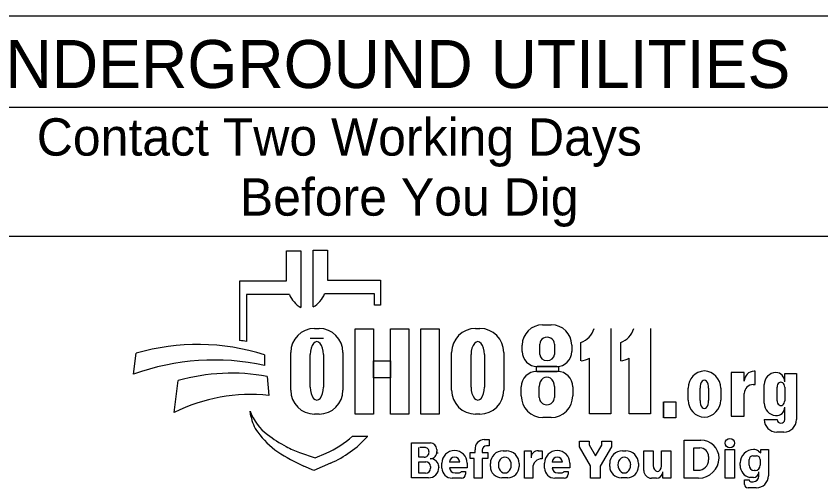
# Model space of a CAD drawing. Extents: x -20.5 to 34, y -66 to 23.9.
# Drawn here: x 15.219 to 18.236, y 1.67 to 3.439 of the extents above; entities that cross this region are included whole.
import ezdxf

# ---------------------------------------------------------------- set-up
doc = ezdxf.new("R2010")
doc.units = 0
doc.layers.add('SH_Data', color=7, linetype='Continuous')
doc.layers.add('SH_Text', color=7, linetype='Continuous')

msp = doc.modelspace()

# ---------------------------------------------------------------- linework, layer by layer
at = {"layer": 'SH_Data'}
for p, q in [((19.1267, 3.4394), (14.8767, 3.4394)), ((14.8767, 3.0978), (19.1267, 3.0978)), ((14.8767, 2.6144), (19.1267, 2.6144))]:
    msp.add_line(p, q, dxfattribs=at)
at = {"layer": 'SH_Text'}
for p, q in [((16.2327, 2.4474), (16.2327, 2.5589)), ((16.2327, 2.5589), (16.2864, 2.5589)), ((16.2864, 2.5589), (16.2864, 2.3468)), ((16.332, 2.3491), (16.332, 2.5612)), ((16.332, 2.5612), (16.3857, 2.5612)), ((16.3857, 2.5612), (16.3857, 2.4497)), ((16.0568, 2.2235), (16.0568, 2.4474)), ((16.0568, 2.4474), (16.2327, 2.4474)), ((16.3857, 2.4497), (16.5849, 2.4497)), ((16.5849, 2.4497), (16.5849, 2.3559)), ((16.082, 2.3959), (16.082, 2.2191)), ((16.2431, 2.3959), (16.082, 2.3959)), ((16.5616, 2.3983), (16.3753, 2.3983)), ((16.5616, 2.3559), (16.5616, 2.3983)), ((16.5849, 2.3559), (16.5616, 2.3559)), ((16.3377, 2.2682), (16.3543, 2.2682)), ((16.9408, 2.2682), (16.9573, 2.2682)), ((17.1923, 2.2822), (17.225, 2.2822)), ((17.4478, 2.2678), (17.4478, 1.9478)), ((17.5967, 2.2678), (17.5967, 1.9478)), ((16.371, 2.2312), (16.3212, 2.2312)), ((17.116, 2.1816), (17.116, 2.2059)), ((17.1821, 2.1702), (17.1821, 2.2095)), ((17.2363, 2.2095), (17.2363, 2.1702)), ((17.3013, 2.2059), (17.3013, 2.1816)), ((17.3362, 2.1471), (17.3362, 2.2152)), ((17.4851, 2.1471), (17.4851, 2.2152)), ((15.6594, 2.0972), (15.6688, 2.1753)), ((16.2482, 2.0367), (16.2482, 2.1787)), ((16.4437, 2.1787), (16.4437, 2.0367)), ((16.8513, 2.0367), (16.8513, 2.1787)), ((17.0468, 2.1787), (17.0468, 2.0367)), ((16.1501, 2.1688), (16.1501, 2.13)), ((16.3212, 2.0481), (16.3212, 2.1705)), ((16.3709, 2.1705), (16.3709, 2.0481)), ((16.9242, 2.0481), (16.9242, 2.1705)), ((16.974, 2.1705), (16.974, 2.0481)), ((17.3686, 1.9478), (17.3686, 2.1564)), ((17.5174, 1.9478), (17.5174, 2.1564)), ((17.2453, 2.1256), (17.172, 2.1256)), ((16.16, 2.0882), (16.1663, 2.0173)), ((17.1702, 2.1073), (17.2475, 2.1073)), ((17.9485, 2.1027), (17.8996, 2.1027)), ((17.8996, 2.1027), (17.8996, 1.9397)), ((17.9485, 2.0711), (17.9485, 2.1027)), ((17.9892, 2.1078), (17.9852, 2.1078)), ((17.9892, 2.0579), (17.9892, 2.1078)), ((18.1, 2.0685), (18.1, 2.0995)), ((18.1, 2.0995), (18.1436, 2.0995)), ((18.1436, 2.0995), (18.1436, 1.9266)), ((15.8112, 1.9527), (15.8259, 2.0728)), ((17.9815, 2.0579), (17.9892, 2.0579)), ((18.0231, 1.9881), (18.0231, 2.0577)), ((17.1123, 2.0154), (17.1123, 2.0494)), ((17.1798, 2.0094), (17.1798, 2.0503)), ((17.2366, 2.0503), (17.2366, 2.0094)), ((17.3054, 2.0494), (17.3054, 2.0154)), ((17.7376, 1.9995), (17.7376, 2.0449)), ((17.7827, 1.9987), (17.7827, 2.0449)), ((17.8148, 2.0449), (17.8148, 1.9987)), ((17.8598, 2.0449), (17.8598, 1.9995)), ((17.9485, 1.9397), (17.9485, 2.025)), ((18.0714, 1.9974), (18.0714, 2.0484)), ((18.1, 2.0484), (18.1, 1.9974)), ((17.6447, 1.9928), (17.6447, 1.9327)), ((18.1, 1.9266), (18.1, 1.973)), ((16.0989, 1.9398), (16.0959, 1.9577)), ((16.3543, 1.9473), (16.3377, 1.9473)), ((16.9573, 1.9473), (16.9408, 1.9473)), ((17.2244, 1.9344), (17.1932, 1.9344)), ((17.4478, 1.9478), (17.3686, 1.9478)), ((17.5967, 1.9478), (17.5174, 1.9478)), ((17.8996, 1.9397), (17.9485, 1.9397)), ((18.0231, 1.9266), (18.0714, 1.9266)), ((18.0968, 1.8799), (18.0699, 1.8799)), ((16.4792, 1.8639), (16.5366, 1.8639)), ((16.9731, 1.8517), (16.9925, 1.8517)), ((16.9925, 1.8517), (16.9925, 1.8287)), ((17.3311, 1.8461), (17.3669, 1.8461)), ((17.3311, 1.8246), (17.3311, 1.8461)), ((17.3669, 1.8461), (17.3669, 1.8325)), ((17.4142, 1.831), (17.4142, 1.8461)), ((17.4142, 1.8461), (17.4501, 1.8461)), ((17.4501, 1.8461), (17.4501, 1.8246)), ((17.7235, 1.8497), (17.7858, 1.8497)), ((17.7235, 1.7069), (17.7235, 1.8497)), ((16.7005, 1.7081), (16.7005, 1.8389)), ((16.7005, 1.8389), (16.7717, 1.8389)), ((16.7285, 1.7854), (16.7285, 1.8223)), ((16.7537, 1.8223), (16.7324, 1.8223)), ((16.7954, 1.8151), (16.7954, 1.8072)), ((16.9398, 1.8033), (16.9398, 1.8137)), ((16.9659, 1.8117), (16.9659, 1.8033)), ((16.9925, 1.8282), (16.9824, 1.8282)), ((17.3724, 1.7536), (17.3311, 1.8246)), ((17.3669, 1.8325), (17.391, 1.7911)), ((17.391, 1.7911), (17.4142, 1.831)), ((17.4501, 1.8246), (17.408, 1.7523)), ((17.7595, 1.7363), (17.7595, 1.8204)), ((17.7595, 1.8204), (17.782, 1.8204)), ((17.8761, 1.814), (17.9118, 1.814)), ((17.8761, 1.7069), (17.8761, 1.814)), ((17.9118, 1.814), (17.9118, 1.7069)), ((18.0099, 1.8144), (18.0386, 1.8144)), ((18.0099, 1.8018), (18.0099, 1.8144)), ((18.0099, 1.8144), (18.0386, 1.8144)), ((18.0386, 1.8144), (18.0386, 1.7158)), ((16.2808, 1.8035), (16.3402, 1.783)), ((16.3402, 1.783), (16.3812, 1.8008)), ((16.7479, 1.7854), (16.7285, 1.7854)), ((16.9205, 1.7803), (16.9205, 1.8033)), ((16.9205, 1.8033), (16.9398, 1.8033)), ((16.9354, 1.7803), (16.9205, 1.7803)), ((16.9354, 1.7069), (16.9354, 1.7803)), ((16.9659, 1.8033), (16.9875, 1.8033)), ((16.9875, 1.7803), (16.9659, 1.7803)), ((16.9659, 1.7803), (16.9659, 1.7069)), ((16.9875, 1.8033), (16.9875, 1.7803)), ((17.0443, 1.8099), (17.0564, 1.8099)), ((17.1245, 1.7069), (17.1245, 1.8096)), ((17.1245, 1.8096), (17.1491, 1.8096)), ((17.1491, 1.8096), (17.1491, 1.7827)), ((17.1763, 1.8096), (17.1902, 1.8096)), ((17.1902, 1.8096), (17.1902, 1.78)), ((17.4917, 1.8099), (17.5039, 1.8099)), ((17.5719, 1.8099), (17.6066, 1.8099)), ((17.5719, 1.7353), (17.5719, 1.8099)), ((17.6066, 1.8099), (17.6066, 1.7545)), ((17.638, 1.7528), (17.638, 1.8099)), ((17.638, 1.8099), (17.6728, 1.8099)), ((17.6728, 1.8099), (17.6728, 1.7069)), ((17.8146, 1.7877), (17.8146, 1.7759)), ((17.9808, 1.791), (17.9935, 1.791)), ((18.0013, 1.8084), (18.0099, 1.8018)), ((16.3342, 1.736), (16.2968, 1.7525)), ((16.3975, 1.7635), (16.3342, 1.736)), ((16.7285, 1.726), (16.7285, 1.7688)), ((16.7285, 1.7688), (16.754, 1.7688)), ((16.7721, 1.7507), (16.7721, 1.7443)), ((16.815, 1.7449), (16.815, 1.7633)), ((16.8816, 1.7673), (16.8431, 1.7673)), ((16.9096, 1.7633), (16.9096, 1.7457)), ((16.9965, 1.7512), (16.9965, 1.762)), ((17.1042, 1.762), (17.1042, 1.7512)), ((17.2, 1.7449), (17.2, 1.7633)), ((17.2665, 1.7673), (17.228, 1.7673)), ((17.2945, 1.7633), (17.2945, 1.7457)), ((17.3724, 1.7069), (17.3724, 1.7536)), ((17.408, 1.7523), (17.408, 1.7069)), ((17.4439, 1.7512), (17.4439, 1.762)), ((17.5517, 1.762), (17.5517, 1.7512)), ((17.9327, 1.7544), (17.9327, 1.7645)), ((17.9662, 1.7552), (17.9662, 1.7764)), ((18.0082, 1.7764), (18.0082, 1.7552)), ((16.7537, 1.726), (16.7285, 1.726)), ((16.8035, 1.7478), (16.8035, 1.7475)), ((16.9096, 1.7457), (16.8432, 1.7457)), ((16.8641, 1.7264), (16.8782, 1.7264)), ((16.8868, 1.732), (16.9036, 1.732)), ((16.9036, 1.732), (16.9036, 1.7222)), ((17.1551, 1.7451), (17.1551, 1.7069)), ((17.2945, 1.7457), (17.2281, 1.7457)), ((17.249, 1.7264), (17.2631, 1.7264)), ((17.2717, 1.732), (17.2886, 1.732)), ((17.2886, 1.732), (17.2886, 1.7222)), ((17.6431, 1.7069), (17.6431, 1.731)), ((17.7751, 1.7363), (17.7595, 1.7363)), ((17.9888, 1.7359), (17.9855, 1.7359)), ((18.003, 1.7148), (18.003, 1.7302)), ((16.7642, 1.7081), (16.7005, 1.7081)), ((16.8884, 1.7069), (16.853, 1.7069)), ((16.9659, 1.7069), (16.9354, 1.7069)), ((17.0615, 1.7085), (17.0393, 1.7085)), ((17.1551, 1.7069), (17.1245, 1.7069)), ((17.2733, 1.7069), (17.2379, 1.7069)), ((17.408, 1.7069), (17.3724, 1.7069)), ((17.5089, 1.7085), (17.4867, 1.7085)), ((17.6191, 1.7069), (17.6002, 1.7069)), ((17.6728, 1.7069), (17.6431, 1.7069)), ((17.7771, 1.7069), (17.7235, 1.7069)), ((17.9118, 1.7069), (17.8761, 1.7069)), ((17.9492, 1.6836), (17.9492, 1.7006)), ((17.9492, 1.7006), (17.9662, 1.7006)), ((17.9827, 1.7097), (17.969, 1.7097)), ((17.973, 1.6936), (17.9819, 1.6936)), ((17.9933, 1.6705), (17.9623, 1.6705))]:
    msp.add_line(p, q, dxfattribs=at)
for points in [[(16.4901, 2.2672), (16.5581, 2.2672), (16.5581, 1.9472), (16.4901, 1.9472)], [(16.6223, 2.2672), (16.6903, 2.2672), (16.6903, 1.9472), (16.6223, 1.9472)], [(16.7356, 2.2672), (16.8044, 2.2672), (16.8044, 1.9472), (16.7356, 1.9472)], [(16.5581, 2.1473), (16.6223, 2.1473), (16.6223, 2.0833), (16.5581, 2.0833)], [(17.1698, 2.1256), (17.2515, 2.1256), (17.2515, 2.1072), (17.1698, 2.1072)], [(17.6472, 1.9928), (17.6913, 1.9928), (17.6913, 1.9327), (17.6472, 1.9327)]]:
    msp.add_lwpolyline(points, close=True, dxfattribs=at)
msp.add_circle((17.8944, 1.8383), 0.0177, dxfattribs=at)
for centre, radius, start, end in [((16.3345, 2.4327), 0.0985, 201.9296, 240.7469), ((16.2839, 2.435), 0.0985, 299.2531, 338.0704), ((16.3377, 2.1787), 0.0895, 90, 180), ((16.3543, 2.1787), 0.0895, 0, 90), ((16.9408, 2.1787), 0.0895, 90, 180), ((16.9573, 2.1787), 0.0895, 0, 90), ((17.1923, 2.2059), 0.0763, 90, 180), ((17.225, 2.2059), 0.0763, 0, 90), ((17.3023, 2.297), 0.0885, 292.5572, 340.7355), ((17.4511, 2.297), 0.0885, 292.5572, 340.7355), ((15.8989, 1.3892), 0.8191, 72.1402, 106.3144), ((15.9286, 1.4145), 0.8191, 79.2074, 81.0007), ((17.172, 2.1816), 0.056, 180, 270), ((17.2453, 2.1816), 0.056, 270, 0), ((15.9619, 1.2581), 0.8919, 77.8238, 109.8274), ((17.3283, 2.2352), 0.0885, 275.1733, 297.0931), ((17.4771, 2.2352), 0.0885, 275.1733, 297.0931), ((16.0258, 1.3685), 0.7322, 79.44, 105.8467), ((17.1702, 2.0494), 0.0579, 90, 180), ((17.2475, 2.0494), 0.0579, 0, 90), ((17.8016, 2.0449), 0.064, 92.5886, 180), ((17.7958, 2.0449), 0.064, 0, 87.4114), ((17.9852, 2.0711), 0.0367, 90, 180), ((18.069, 2.0577), 0.0459, 92.6865, 180), ((18.065, 2.0685), 0.0351, 0, 86.9262), ((17.9815, 2.025), 0.033, 90, 180), ((16.3377, 2.0367), 0.0895, 180, 270), ((16.3543, 2.0367), 0.0895, 270, 0), ((16.9408, 2.0367), 0.0895, 180, 270), ((16.9573, 2.0367), 0.0895, 270, 0), ((16.0979, 1.3852), 0.6357, 83.8248, 116.8021), ((17.1932, 2.0154), 0.081, 180, 270), ((17.2244, 2.0154), 0.081, 270, 0), ((17.8016, 1.9995), 0.064, 180, 267.4114), ((17.7958, 1.9995), 0.064, 272.5886, 0), ((18.0694, 1.9881), 0.0463, 180, 265.7132), ((18.0688, 1.973), 0.0313, 264.7825, 0), ((16.2832, 2.0298), 0.2008, 201.0457, 232.5314), ((16.2402, 1.9639), 0.1433, 189.6817, 216.0884), ((18.0699, 1.9266), 0.0468, 180, 270), ((18.0968, 1.9266), 0.0468, 270, 0), ((16.3739, 2.0613), 0.3088, 216.0884, 235.7167), ((16.4758, 2.281), 0.5173, 232.5314, 241.794), ((16.2378, 2.1313), 0.3602, 293.4582, 312.0712), ((16.2378, 2.1313), 0.401, 293.4582, 317.8286), ((16.9731, 1.8181), 0.0335, 90, 187.5187), ((17.7858, 1.7814), 0.0682, 0.9944, 90), ((16.3906, 2.1222), 0.3371, 241.794, 250.9821), ((16.7497, 1.8054), 0.0169, 357.8325, 90), ((16.7717, 1.8151), 0.0238, 0, 90), ((16.8623, 1.7633), 0.0473, 0, 180), ((16.9824, 1.8117), 0.0165, 90, 180), ((17.2472, 1.7633), 0.0473, 0, 180), ((17.782, 1.7877), 0.0327, 0, 90), ((17.9826, 1.7645), 0.0499, 89.0934, 180), ((17.984, 1.7861), 0.0283, 52.1415, 91.2046), ((16.5404, 2.3056), 0.6044, 235.7167, 246.2325), ((16.7479, 1.8041), 0.0187, 270, 2.0582), ((16.7713, 1.8044), 0.0243, 270, 6.6529), ((16.7714, 1.748), 0.0321, 4.0748, 90), ((16.7819, 1.8029), 0.0175, 347.4023, 0), ((16.8624, 1.7663), 0.0193, 2.9632, 177.0368), ((17.0443, 1.762), 0.0478, 90, 180), ((17.0564, 1.762), 0.0478, 0, 90), ((17.176, 1.7827), 0.0269, 89.2449, 180), ((17.19, 1.7451), 0.0349, 89.6033, 180), ((17.2473, 1.7663), 0.0193, 2.9632, 177.0368), ((17.4917, 1.762), 0.0478, 90, 180), ((17.5039, 1.762), 0.0478, 0, 90), ((17.7771, 1.7839), 0.0769, 270, 359.0635), ((17.9808, 1.7764), 0.0146, 90, 180), ((17.9935, 1.7764), 0.0146, 0, 90), ((16.754, 1.7507), 0.0181, 0, 90), ((16.7705, 1.7478), 0.033, 0, 11.7502), ((17.0393, 1.7512), 0.0428, 180, 270), ((17.0615, 1.7512), 0.0428, 270, 0), ((17.4867, 1.7512), 0.0428, 180, 270), ((17.5089, 1.7512), 0.0428, 270, 0), ((17.7751, 1.7759), 0.0395, 270, 0), ((17.9783, 1.7544), 0.0457, 180, 258.2203), ((17.9855, 1.7552), 0.0193, 180, 270), ((17.9888, 1.7552), 0.0193, 270, 0), ((16.7537, 1.7443), 0.0184, 270, 0), ((16.7642, 1.7475), 0.0393, 270, 0), ((16.853, 1.7449), 0.038, 180, 270), ((16.8641, 1.7474), 0.021, 184.827, 270), ((16.8782, 1.7358), 0.00938, 270, 335.9979), ((16.8884, 1.7222), 0.0152, 270, 0), ((17.2379, 1.7449), 0.038, 180, 270), ((17.249, 1.7474), 0.021, 184.827, 270), ((17.2631, 1.7358), 0.00938, 270, 335.9979), ((17.2733, 1.7222), 0.0152, 270, 0), ((17.6002, 1.7353), 0.0284, 180, 270), ((17.6191, 1.731), 0.024, 270, 0), ((17.9827, 1.73), 0.0203, 270, 0), ((17.973, 1.7004), 0.00682, 180, 270), ((17.9819, 1.7148), 0.0212, 270, 0), ((17.9933, 1.7158), 0.0453, 270, 0), ((17.9623, 1.6836), 0.0131, 180, 270)]:
    msp.add_arc(centre, radius, start, end, dxfattribs=at)
for centre, major_axis, ratio, start_param, end_param in [((17.2092, 2.2095), (0.0271, 0), 0.969373, 0, 3.141593), ((16.3461, 2.1705), (0, 0.0484), 0.514403, 4.712389, 7.853982), ((16.9491, 2.1705), (0, 0.0484), 0.514403, 4.712389, 7.853982), ((17.2092, 2.1702), (0.0271, 0), 0.818453, 3.141593, 6.283185), ((17.2082, 2.0503), (0, 0.0358), 0.794529, 4.712389, 7.853982), ((17.7987, 2.0449), (0, 0.0291), 0.553236, 4.712389, 7.853982), ((18.0857, 2.0484), (0, 0.0184), 0.777179, 4.712389, 7.853982), ((16.3461, 2.0481), (0, 0.0484), 0.514403, 1.570796, 4.712389), ((16.9491, 2.0481), (0, 0.0484), 0.514403, 1.570796, 4.712389), ((17.2082, 2.0094), (0.0284, 0), 0.959837, 3.141593, 6.283185), ((17.7987, 1.9987), (0, 0.0308), 0.522014, 1.570796, 4.712389), ((18.0857, 1.9974), (0, 0.0184), 0.777179, 1.570796, 4.712389), ((18.0857, 1.9266), (0.0143, 0), 0.959012, 3.141593, 6.283185), ((17.0508, 1.7566), (0, 0.029), 0.832186, 4.712389, 7.853982), ((17.4983, 1.7566), (0, 0.029), 0.832186, 4.712389, 7.853982), ((17.0508, 1.7566), (0, 0.0302), 0.797287, 1.570796, 4.712389), ((17.4983, 1.7566), (0, 0.0302), 0.797287, 1.570796, 4.712389), ((17.6223, 1.7553), (-0.0011, 0.0231), 0.679042, 1.570796, 4.575961)]:
    msp.add_ellipse(centre, major_axis=major_axis, ratio=ratio, start_param=start_param, end_param=end_param, dxfattribs=at)

# ---------------------------------------------------------------- texts
for s, height, p in [('UNDERGROUND UTILITIES', 0.18, (15.0048, 3.1697)), ('Contact Two Working Days', 0.14, (15.2963, 2.9162)), ('Before You Dig', 0.14, (16.0575, 2.6912))]:
    msp.add_text(s, height=height, dxfattribs=at).set_placement(p)

doc.saveas('drawing.dxf')
